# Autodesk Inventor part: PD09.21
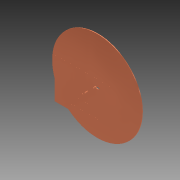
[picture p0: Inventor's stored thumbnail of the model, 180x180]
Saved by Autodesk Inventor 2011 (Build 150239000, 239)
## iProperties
Created: 2014-06
Part Number: PD09.21
Document SubType Name: Modeling
Designer: Evgeny
Density: 1 g/cm^3
Author: Evgeny
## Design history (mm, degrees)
sketch "Эскиз1"
  geometry: L1 (-46.5, 33.5)-(46.5, 33.5); L2 (46.5, 33.5)-(46.5, -33.5); L3 (46.5, -33.5)-(-46.5, -33.5); L4 (-46.5, -33.5)-(-46.5, 33.5); L5 (27.5, 22.5)-(27.5, -23.5); L6 (27.5, -23.5)-(-27.5, -23.5); L7 (-27.5, -23.5)-(-27.5, 22.5); L8 (17.5, 22.5)-(17.5, -17.5); L9 (17.5, -17.5)-(-17.5, -17.5); L10 (-17.5, -17.5)-(-17.5, 22.5); L11 (-27.5, 22.5)-(-17.5, 22.5); L12 (17.5, 22.5)-(27.5, 22.5); L13 (-8, 10)-(8, 10); L14 (8, 10)-(8, -10); L15 (-8, -10)-(-8, 10); L16 (-3, -10)-(-3, 7); L17 (-3, 7)-(3, 7); L18 (3, 7)-(3, -10); L19 (-8, -10)-(-3, -10); L20 (3, -10)-(8, -10); C1 r 0.85 at (0, 0); 1 further point
  constraints: 40 end point, 8 equal length, 4 perpendicular, 2 collinear, 2 horizontal, 1 centre point, 1 coincident
  dimensions: "d1" = 67 distance between parallel lines of L3 L1; "d2" = 33.5 distance from line of L3 point (0, 0); "d3" = 46.5 distance from line of L4 point (0, 0); "d4" = 1.7 diameter of C1; "d5" = 55 distance between parallel lines of L5 L7; "d6" = 46 distance between parallel lines of L11 L6; "d7" = 10 distance between parallel lines of L10 L7; "d8" = 10 distance between parallel lines of L8 L5; "d9" = 6 distance between parallel lines of L6 L9; "d10" = 27.5 distance from line of L7 point (0, 0); "d11" = 10 distance between parallel lines of L3 L6; "d12" = 93 distance between parallel lines of L2 L4; "d13" = 20 distance between parallel lines of L20 L13; "d14" = 5 distance between parallel lines of L18 L14; "d15" = 5 distance between parallel lines of L15 L16; "d16" = 16 distance between parallel lines of L14 L15; "d17" = 8 distance from line of L15 point (0, 0); "d18" = 10 distance from line of L13 point (0, 0); "d19" = 3 distance between parallel lines of L17 L13
extrude "Выдавливание1" new body sketch "Эскиз1" distance "d20" = 0.035; taper "d21" = 0 deg
extrude "Выдавливание2" join sketch "Эскиз1" distance "d22" = 1; taper "d24" = 0 deg; dims "d23" = 24.035, "d25" = 0
node "РабПлоскость2"
sketch "Эскиз2"
  geometry: C1 r 4.5 at (0, 0); C2 r 75 at (0, 0); 1 further point
  constraints: 2 centre point, 2 coincident
  dimensions: "d28" = 9 diameter of C1; "d29" = 150 diameter of C2
extrude "Выдавливание3" join sketch "Эскиз2" distance "d30" = 1; taper "d31" = 0 deg
node "Твердое тело1"
other parameters: "d27" = -24
